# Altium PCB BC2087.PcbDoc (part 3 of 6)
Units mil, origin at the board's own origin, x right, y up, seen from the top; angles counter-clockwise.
Board outline 7401.57 x 1181.1 mil, 6 copper layers (Top Copper, Signal Layer 1, Signal Layer 2, Signal Layer 3, Signal Layer 4, Bottom Copper), stack 62.874 mil thick; 302 components, 237 nets, 1184 pads, 867 vias.
Unrouted connection lines stored in the file: 315.
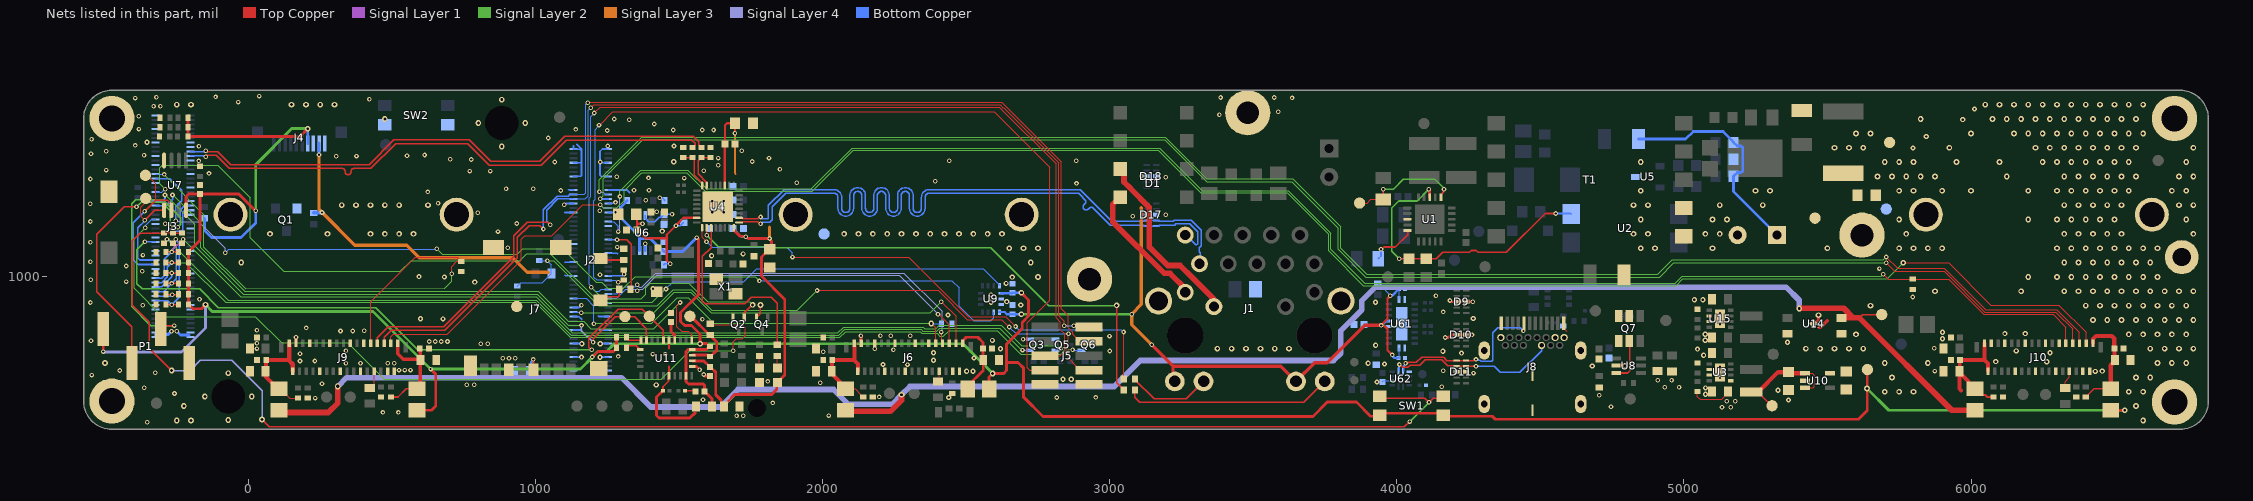
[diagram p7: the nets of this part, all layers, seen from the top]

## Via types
v1: diameter 20, hole 10, Top Copper to Bottom Copper, 273 vias
v2: diameter 16, hole 8, Top Copper to Bottom Copper, tented both sides, 243 vias
v3: diameter 15.98, hole 7.99, Top Copper to Bottom Copper, tented both sides, 201 vias
v4: diameter 18, hole 8, Top Copper to Bottom Copper, tented both sides, 70 vias
v5: diameter 16, hole 7.95, Top Copper to Bottom Copper, tented both sides, 36 vias
v6: diameter 20, hole 10, Top Copper to Bottom Copper, tented both sides, 26 vias
v7: diameter 16, hole 8, Top Copper to Bottom Copper, 17 vias
v8: diameter 19.68, hole 11.81, Top Copper to Bottom Copper, tented both sides, 1 vias

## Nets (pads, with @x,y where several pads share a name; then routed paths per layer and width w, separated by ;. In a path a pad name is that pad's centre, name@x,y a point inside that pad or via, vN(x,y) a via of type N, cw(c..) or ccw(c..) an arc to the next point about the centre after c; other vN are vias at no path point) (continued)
1V8: C12.2 C18.2 C19.2 C52.2 C60.2 C120.2 FB5.1 FB8.1 FB11.1 J4.7 P1.1 R1.2 R2.2 R7.2 R9.2 R16.2 R31.2 R50.2 R68.2 R72.1 R73.1 R79.1 R128.2 R129.2 R130.2 SW1.2 SW1.4 TP16.1 U6.3 U7.8 U9.5 U10.5 U11.5 U11.28 | length 11933.2
  Top Copper w10: P1.1@-506.43,818.06 -506.43,740.43 v2(-506,740) ; U7.8@-217.52,1232.28 -217.52,1280.29 -208.68,1289.13 C120.2@-169.29,1289.13 ; R130.2@-210.63,1554.35 -211.12,1553.85 -211.12,1489.67 R129.2@-211.61,1489.17 179.17,1489.17 v6(206,1516) ; v6(-150,903.41) -164.41,889 -194.06,889 R1.2@-208.66,903.6 R2.2@-208.66,939.96 R7.2@-208.66,977.36 R9.2@-208.66,1013.78 R16.2@-208.66,1050.2 R68.2@-208.66,1086.61 -208.66,1088.58 -169.29,1127.95 C120.2@-169.29,1289.13 ; v5(25,1230) -34.13,1289.13 C120.2@-169.29,1289.13 ; FB8.1@586.61,535.43 637.43,535.43 652,550 652,661 v5(634,679) ; v5@1197.86,721 1216.86,740 1270.25,740 1281.28,751.03 R73.1@1281.28,753 R72.1@1281.28,790 ; v5(1561,1137) 1567,1131 1567,938 1505,876 1505,845 1519.21,830.79 1543.2,830.79 1573,800.98 v6(1573,767) 1574.05,768.05 1594.7,768.05 R31.2@1605.03,757.72 ; R31.2@1607,757.72 R31.2@1605.03,757.72 ; C18.2@1614.32,548.35 1614.32,575.43 C19.2@1588.75,601 1588.75,622.39 1584.14,627 1532,627 1523.9,635.1 U11.28@1523.9,656 1523.9,740.75 1530.19,747.05 U11.5@1546.04,747.05 1594.36,747.05 R31.2@1605.03,757.72 ; FB11.1@2579.61,610.24 2579.61,651.55 v6(2592,663.94) 2630.47,663.94 2640,673.47 2640,701.74 ; v6(2691.86,944.88) 2717,919.75 2717,863.6 2695,841.6 2695,820.59 2640,765.59 2640,701.74 ; 5638.56,536.95 5638.56,534.56 ; TP16.1@5638.56,676.56 5638.56,534.56 ; FB5.1@6486.76,535.43 v6(6535.57,535.43) ; 2640,701.74 2680.26,701.74 2700,682 2700,581 2767,514 3707.62,514 3757.62,564 3859,564 3908.24,514.76 3937.08,514.76 3941,510.84 3955.16,525 4147.32,525 4161.47,510.84 4165.39,514.76 4332.24,514.76 4343,504 5608,504 5638.56,534.56
  Signal Layer 2 w10: v6(-150,903.41) -126.59,880 433,880 v5(634,679) 1156,679 v5@1197,720 ; v5(25,1230) 25,1391 150.5,1516.5 205.5,1516.5 v6(206,1516) ; v5(1197,721) 1216,740 1247,740 1274,767 v6(1573,767) 2488.94,767 v6(2592,663.94) ; v6(5638,611) 5713.57,535.43 v6(6535.57,535.43)
  Signal Layer 4 w10: v2(-506,740) -504,738 -233.56,738 -150,821.56 v6(-150,903.41)
  Bottom Copper w10: R79.1@-153.29,1203.61 -153.29,1161.6 -128.7,1137 -26,1137 25,1188 v5(25,1230) ; J4.7@206.03,1465.03 v6(206,1516) ; R50.2@1318.5,1266.18 1318.5,1264.21 1297.68,1243.39 1297.68,1205.5 1362.09,1141.09 1362.09,1133 ; U6.3@1362.09,1092.12 1362.09,1133 ; v5(1561,1137) 1512.18,1088.18 C52.2@1446.73,1088.18 1439.53,1095.39 1437.61,1095.39 1400,1133 1362.09,1133 ; U9.5@2621.71,942.91 2621.79,942.99 2659.53,942.99 C12.2@2661.42,944.88 v6(2691.86,944.88)
  other v4: 2527,717.75
1V8_CAM_M: C71.2 C72.2 FB11.2 J6.1 | length 275.2
  Top Copper w9.84: J6.1@2488.04,768.34 2489.02,769.32 2489.02,778.54 2500.07,789.59 2540.21,789.59 2557.84,771.95 C71.2@2557.84,750.22 2558.54,749.52 C72.2@2558.54,711.24 ; FB11.2@2504.81,610.24 2504.81,619.67 2559.23,674.1 C72.2@2559.23,710.55
1V8_L: C80.2 C81.2 FB5.2 J10.1 R35.1 | length 379
  Top Copper w5.91: R35.1@6399.75,581.69 6401.72,581.69 6407.63,587.6 6407.63,589.57 6428.29,610.24 FB5.2@6486.76,610.24
  Top Copper w15: J10.1@6425.05,768.34 6425.2,768.49 6425.2,783.46 6435.77,794.04 6490.43,794.04 6499.22,785.25 C80.2@6499.22,750.22 6500.2,749.23 6500.2,711.53 C81.2@6501.19,710.55 6501.19,706.61 6486.76,692.18 FB5.2@6486.76,610.24
1V8_R: C86.2 C87.2 FB8.2 J9.1 R40.1 | length 372.5
  Top Copper w5.91: R40.1@495.79,581.69 520.67,581.69 549.21,610.24 FB8.2@586.61,610.24
  Top Copper w11.81: J9.1@519.54,768.34 519.54,732.28 539.22,712.6 596.49,712.6 C87.2@598.55,710.55 ; FB8.2@586.61,610.24 598.43,622.05 598.43,710.42 C87.2@598.55,710.55 ; C86.2@596.46,750.22 597.5,749.17 597.5,711.59 C87.2@598.55,710.55
2V8: C66.2 FB4.1 FB7.1 FB10.1 TP23.1 U14.1 | length 6907.7
  Top Copper w5.91: 5611.22,857.28 5622.54,868.6 TP23.1@5688.98,868.6
  Top Copper w11.81: 5470.47,823.82 5475.39,823.82 5499.02,847.44
  Top Copper w19.68: FB7.1@106.3,535.43 114.17,527.56 277.63,527.56 310.93,560.86 v8(310.93,618.46) ; FB10.1@2079.46,535.43 2083.39,531.5 2236.22,531.5 2274.55,569.82 2274.55,589.51 v6(2274.61,589.57) ; v6@5401.68,889.87 5401.72,889.82 5402.64,890.75 5556.86,890.75 5590.32,857.28 ; C66.2@5549.21,857.28 5590.32,857.28 ; FB4.1@6013.85,535.43 5933.07,535.43 5611.22,857.28 5590.32,857.28
  Signal Layer 4 w19.68: v8(310.93,618.46) 341.47,649 1298.88,649 1400.88,547 1643.38,547 1704.38,608 2038,608 2090,556 2241.04,556 v6(2274.61,589.57) ; v6@2274.55,589.63 v6(2274.61,589.57) ; v6(5401.57,889.76) 5401.57,918.53 5355.54,964.57 3925.2,964.57 3877.95,917.32 3877.95,885.83 3805.12,812.99 3805.12,734.25 3779.53,708.66 3106.3,708.66 3015.75,618.11 2653.54,618.11 2653.19,618.46 2303.5,618.46 v6(2274.61,589.57)
2V8_CAM_M: C75.2 C77.2 FB10.2 J6.32 J6.33 R60.1 | length 373.9
  Top Copper w4: FB10.2@2079.46,610.24 2112.68,610.24 2132.63,590.29 2132.63,588.32 2139.49,581.46 R60.1@2141.46,581.46
  Top Copper w13.78: FB10.2@2079.46,610.24 2079.46,614.23 2031.6,662.09 C77.2@2031.6,671.48 2032.38,672.26 2032.38,709.76 C75.2@2033.16,710.55 2108.33,710.55 ; J6.33@2110.09,768.34 2110.09,712.3 2108.33,710.55 ; J6.32@2122.19,671.88 2122.19,696.68 2108.33,710.55
2V8_L: C82.2 C83.2 FB4.2 J10.32 J10.33 R71.2 | length 454.7
  Top Copper w7.87: FB4.2@6013.85,610.24 6035.5,588.58 6049.3,588.58 6056.19,581.69 R71.2@6078.82,581.69
  Top Copper w13.78: 5965.8,604.89 5959.74,610.95 C83.2@5959.74,667.54 ; FB4.2@6013.85,610.24 6009.91,610.24 5991.21,628.94 5991.21,636.07 C83.2@5959.74,667.54 ; J10.33@6047.1,768.34 6047.1,710.55 ; J10.32@6059.2,671.88 6059.2,698.44 6047.1,710.55 ; C83.2@5959.74,667.54 C83.2@5959.74,671.48 5960.72,672.46 5960.72,709.56 C82.2@5961.71,710.55 6047.1,710.55
2V8_R: C88.2 C89.2 FB7.2 J9.32 J9.33 R41.2 | length 383.7
  Top Copper w4: FB7.2@106.3,610.24 110.24,610.24 142.72,577.76 R41.2@172.6,577.76
  Top Copper w15: FB7.2@106.3,610.24 102.36,610.24 59.47,653.13 C89.2@59.47,671.48 60.45,672.46 60.45,709.56 C88.2@61.44,710.55 138.67,710.55 ; J9.33@141.58,768.34 141.58,713.46 138.67,710.55 ; J9.32@153.69,671.88 153.69,695.52 138.67,710.55
3V3: C10.2 C15.2 C16.2 C17.2 C21.2 C34.2 C38.2 C39.2 C40.2 C41.2 C53.2 C55.2 C58.2 C59.2 C74.2 C97.2 D16.2 J1.15 J1.17 J4.9 J7.4 L4.2 R28.1 R29.1 R33.2 R46.1 R49.1 R186.2 TP7.1 U3.5 U4.11 U4.23 U4.32 U6.7 U9.8 U10.1 U10.3 U11.3 U61.1 U61.6 U61.10 | length 6595.4
  Top Copper w4: R33.2@5047.24,600.7 5047.24,582.76 5057,573 5132.39,573 5153.54,594.15 C15.2@5153.54,600.7 ; U10.3@5422.24,613.35 5450.79,613.35 5454.72,617.28 5454.72,656.65 5446.85,664.53 U10.1@5422.24,664.53
  Top Copper w5.91: L4.2@5257.87,598.73 TP7.1@5294.44,562.16 ; TP7.1@5295.28,562.99 TP7.1@5300.68,557.58 ; TP7.1@5300.68,560.29 TP7.1@5300.68,557.58 ; TP7.1@5307.09,551.18 TP7.1@5300.68,557.58
  Top Copper w7.87: v3(992.13,712.6) 992.13,676.4 J7.4@992.34,676.18 ; C21.2@1352.66,1219.93 1352.66,1186.71 ; v3(1372.32,1185.63) 1353.74,1185.63 1352.66,1186.71 ; v3(1468.5,1046) 1468.5,1046.46 1456.81,1058.15 1456.81,1134.91 ; U4.23@1561.32,1205.67 1515.21,1205.67 1488.83,1179.29 v3(1488.83,1178.46) 1487.94,1178.46 1456.81,1147.33 1456.81,1134.91 ; C40.2@1657.52,1464.3 C40.2@1659.58,1462.25 ; U4.11@1658.76,1318.86 1658.76,1461.43 C40.2@1659.58,1462.25 ; v3(1694.2,1500.23) 1694.04,1500.39 C39.2@1694.04,1535 1666.32,1535 1659.58,1528.26 C40.2@1659.58,1462.25 ; v3(3945.31,831) 3945.31,832.28 v3@3949.41,836.38 ; v3(3976.51,933.95) 3967.36,924.81 3967.36,854.33 v3@3949.41,836.38 ; v3(3983.61,728.35) 3967.36,744.59 3967.36,818.43 v3@3949.41,836.38 ; 1352.66,1186.71 C34.2@1352.66,1163.86 1381.61,1134.91 1456.81,1134.91
  Top Copper w9.84: U4.32@1691.24,1162.36 1712.19,1141.41 1731.11,1141.41 v3(1732.28,1140.24) 1733.95,1140.24 1740.32,1133.86 v3(1814.96,1133.86) 1814.96,1132.19 1821.49,1125.67 1821.49,1102.76 C38.2@1814.96,1096.24 1812.99,1096.24 1786.35,1069.6 1786.35,1003.1 1867.72,921.74 1867.72,658.62 D16.2@1841.97,632.87
  Top Copper w10: U11.3@1546.04,707.68 1585.07,707.68 C17.2@1607,685.75 1612.24,680.51 1614.49,680.51 1627.24,667.76 1627.24,589.76 1646.66,570.34 1646.66,557.13 C16.2@1655.44,548.35 1655.44,552.29 1664.22,561.07 1664.64,561.07 1694.57,591 1823,591 1839.98,607.98 1839.98,630.89 D16.2@1841.97,632.87
  Top Copper w11.81: v3(3145.67,763.78) 3220.26,689.19 ; J1.15@3226.57,635.89 3220.26,642.2 3220.26,689.19 ; v3(3945.31,831) 3887.35,831 3757.14,700.79 3713.52,700.79 J1.17@3648.62,635.89 3595.32,689.19 3220.26,689.19
  Top Copper w15.75: L4.2@5234.25,598.73 5257.87,598.73 5327.83,668.69 C59.2@5364.17,668.69 5368.33,664.53 U10.1@5422.24,664.53
  Signal Layer 2 w10: v6(2691.86,870.08) 3075.64,870.08 v3(3076,870.44)
  Signal Layer 3 w5: 1812.94,1176.07 1814.96,1174.05
  Signal Layer 3 w5.91: v3(1694.2,1500.23) 1694.2,1360.81 1696.33,1358.67
  Signal Layer 3 w9.84: v3(1814.96,1133.86) 1814.96,1174.05
  Signal Layer 3 w11.81: v3@245.43,1424.06 245.43,1234.88 v3(255.77,1224.54) 370.08,1110.24 551.18,1110.24 594.49,1066.93 920.18,1066.93 971.36,1015.75 1043.31,1015.75 ; 3110,1240.73 3110,904.44 v3(3076,870.44) 3076,833.45 v3(3145.67,763.78)
  Bottom Copper w4: R186.2@3933.54,977.26 3942.37,968.44 3945.31,968.44 v3@3974.21,939.53 ; v3@3974.21,939.49 v3@3976.47,937.24 ; C97.2@4006.09,956.69 C97.2@4006.88,956.69 4007.52,956.05 U61.10@4007.52,921.55 ; C58.2@4006.34,717.61 4007.52,718.79 U61.1@4007.52,752.26
  Bottom Copper w4.02: v3(3976.51,933.95) v3@3976.51,937.24
  Bottom Copper w5: U6.7@1381.77,1214.17 1381.77,1204.32 1389.05,1197.04 1389.05,1195.73 1392.86,1191.92 1414.76,1191.92 1431.33,1208.49 1437.12,1208.49 C53.2@1446.73,1218.1 1447.26,1218.63 v3(1475.13,1218.63) ; v3(1488.83,1178.46) 1503.26,1178.46 1513.78,1188.98 R29.1@1515.75,1188.98 ; C41.2@1688.2,1169.33 1716.79,1140.74 1731.78,1140.74 v3(1732.28,1140.24)
  Bottom Copper w5.91: v3(1432.28,1275.59) 1440.94,1275.59 1448.82,1267.72 R49.1@1448.82,1266.18 ; R46.1@1446.73,1042.91 1449.82,1046 v3(1468.5,1046) ; C74.2@3885.83,834.65 3889.47,831 v3(3945.31,831) 3947.24,832.93 3951.38,832.93 3965.2,846.75 U61.6@3972.09,846.75
  Bottom Copper w7.87: C55.2@984.25,669.69 984.25,702.53 992.13,710.4 v3(992.13,712.6) ; U9.8@2615.31,877.46 2633.8,877.46 2641.18,870.08 C10.2@2661.42,870.08 v6(2691.86,870.08) ; v3(3976.51,933.95) 3978.06,935.51 3984.9,935.51 C97.2@4006.09,956.69 ; v3(3983.61,728.35) 3985.16,726.79 3985.16,724.42 3991.98,717.61 C58.2@4006.34,717.61
  Bottom Copper w11.81: R28.1@226.42,1222.99 253.09,1222.99 254.64,1224.54 v3(255.77,1224.54) ; v3(245.43,1425.2) J4.9@245.43,1465
  other v2: 5132.68,545.77 5163.39,545.77 5149.61,566.93 5178.35,566.93
5V_LED: D6.2 R55.1 | length 44
  Top Copper w4: R55.1@1779.53,724.41 1779.53,686.02 D6.2@1783.46,682.09
5V_PoE: C7.1 C9.2 C26.2 L1.2 Q7.1 Q7.2 Q7.5 Q7.6 R14.2 R24.2 TP6.1 U8.3 | length 942.6
  Top Copper w5.91: U8.3@4763.78,665.35 4804.68,665.35 4811.39,672.07 4811.39,776.21 Q7.2@4810.04,777.56
  Bottom Copper w9.84: C26.2@4842.09,1480.31 5006.01,1480.31 5032.71,1507.02 5136.68,1507.02 5173.23,1470.47 R14.2@5173.23,1468.5 5173.23,1468.43 5186.02,1455.64 5198.96,1455.64 5204.72,1449.87 5204.72,1369.02 5198.96,1363.26 5186.02,1363.26 5173.23,1350.46 R24.2@5173.23,1350.39 5173.23,1297.24 C7.1@5324.8,1145.67
2485_PGOOD: J2.37 J5.5 Q2.1 | length 3825.1
  Top Copper w4.02: v3(1204.4,1571.11) 1224.62,1591.33 2615.26,1591.33 2812.99,1393.6 2812.99,857.71 2827.86,842.84 2827.86,816.81 2842.29,802.38 2842.29,773.56 2842.43,773.41 2842.43,741.18 2826.65,725.39 J5.5@2774.61,725.39
  Top Copper w5: Q2.1@1726.68,859.02 1726.68,875.6 1753.84,902.75 v6(1756,902.75)
  Signal Layer 2 w4.02: v3(1194,964) 1234,924 1367.98,924 1384,940.02 1384,963 1399,978 1534,978 1599,913 1745.75,913 v6(1756,902.75)
  Bottom Copper w4.02: v3(1204.4,1571.11) 1204.4,1570.55 1191.36,1557.51 1191.36,1279.64 1186.72,1275 1186.72,974.51 1194,967.24 v3(1194,964) 1207.44,950.56 1221.91,950.56 1228.04,956.69 J2.37@1252.95,956.69
2485_WAKEUP: J2.41 J5.7 R62.1 | length 3119.3
  Top Copper w4.02: v3(1220.54,1528.98) 1223.07,1528.98 1269.38,1575.3 2597.93,1575.3 2791.34,1381.89 2791.34,918.31 2712.6,839.57 2712.6,684.13 2721.34,675.39 J5.7@2774.61,675.39
  Top Copper w6: v3(1287.4,981.49) 1289.31,983.4 1301.76,983.4 R62.1@1307.09,988.73
  Bottom Copper w4.02: v3(1220.54,1528.98) 1220.54,1525.86 1208.09,1513.41 1208.09,1271.25 1202.76,1265.92 1202.76,999.02 1212.05,989.72 1251.42,989.72 1254.49,986.65 1256.02,988.19 1277.46,988.19 1284.16,981.49 v3(1287.4,981.49)
BMI270_INT_1V8: J3.66 U9.4 | length 3456.8
  Signal Layer 2 w4: v5(-290.42,1305.59) -310,1325.17 -310,1380 -301.35,1388.65 -107.15,1388.65 6.18,1275.32 6.18,1136 123.18,1019 529,1019 566.61,1056.61 944.61,1056.61 969.43,1081.43 1051.57,1081.43 1222,911 1407,911 v2(1454,958)
  Bottom Copper w4: -309.72,1295.28 -302.35,1295.28 -292.03,1305.59 v5(-290.42,1305.59) ; v2(1454,958) 1479.42,983.42 1724.42,983.42 1770,1029 2559.74,1029 2615.31,973.43 U9.4@2615.31,969
  Bottom Copper w5: J3.66@-324.02,1295.28 -309.72,1295.28
BMI270_WAKE_1V8: J3.72 U9.9 | length 3348.3
  Signal Layer 2 w4: v3(655.51,1098.43) 674.94,1079 936.73,1079 955.17,1097.44 1094.51,1097.44 1210.95,981 1231,981 1252,960 1305.44,960 1346.86,1001.42 1764.11,1001.42 v3(1779.53,986)
  Signal Layer 4 w4: v3(-253.94,1195.8) -251.64,1193.5 -242.23,1193.5 -241.28,1192.55 -174.35,1192.55 -81.69,1099.9 v3(-81.69,1084.65)
  Bottom Copper w4: v3(-81.69,1084.65) -80.4,1084.65 -68.59,1096.46 653.54,1096.46 v3(655.51,1098.43) ; v3(1779.53,986) 1780.53,987 2449.91,987 2475,961.91 2475,898.5 2526.5,847 2585,847 2595.63,857.63 U9.9@2595.63,877.46
  Bottom Copper w5: J3.72@-324.02,1342.52 -300.01,1342.52 -274.42,1342.51 -233,1301.09 -233,1264.99 -253.94,1244.05 v3(-253.94,1195.8)
BNO08x_BOOTN_1V8: J3.54 R32.2 | length 2775.7
  Top Copper w4: R32.2@1608,836.69 1611.68,833 1721.42,833 1730.42,824 1730.42,795.42 1719,784 1698.4,784 1688,773.6 v2(1688,742.95)
  Signal Layer 2 w4: v2(-360,1171.49) -398,1133.49 -398,960 -300,862 24,862 116,770 346.28,770 472.36,643.92 1436.92,643.92 1535.95,742.95 v2(1688,742.95)
  Bottom Copper w4: v2(-360,1171.49) -360,1178.39 -337.6,1200.79 J3.54@-324.02,1200.79
BNO08x_BOOTN_1V8_1: R31.1 R32.1 TP26.1 U11.4 | length 258.9
  Top Copper w10: TP26.1@1537,862.91 1540.44,862.91 1606.03,797.32 R32.1@1609.97,797.32 ; U11.4@1546.04,727.36 1599.95,727.36 1605.03,722.28 1608.97,722.28 1631,744.32 1631,773 1608,796 R32.1@1608,797.32
BNO08x_INT_1V8: J3.62 TP35.1 U11.14 | length 2095.1
  Top Copper w5: v5(1200,772) v5(1200,772) 1199.96,783.96 1277.91,861.91 TP35.1@1311.02,861.91 1344.37,861.91 1386.1,820.17 U11.14@1386.1,779.04
  Signal Layer 2 w4: v5(-291,1285.43) -188.3,1182.73 -188.3,1109.3 -18,939 1004.89,939 1112.89,831 v5(1159.74,831)
  Signal Layer 4 w5: v5(1159.74,831) 1159.51,830.76 1159.51,812.49 v5(1200,772)
  Bottom Copper w5: J3.62@-324.02,1263.78 -301.64,1263.78 -291,1274.42 v5(-291,1285.43)
BNO08x_RSTn_1V8: J3.44 TP34.1 U11.11 | length 2285.2
  Top Copper w5: v5(1195,746) 1193.78,746 1185.5,754.28 1185.5,785.5 1288.09,888.09 1370.81,888.09 1445.16,813.75 U11.11@1445.16,779.04
  Signal Layer 2 w5: v5(-361.07,1122.05) -389,1094.12 -389,977 -370,958 -170,958 -105,893 443,893 590,746 v5(1195,746)
  Bottom Copper w6: v5(-361.07,1122.05) J3.44@-324.02,1122.05
BNO08x_WAKE_1V8: J3.60 U11.6 | length 2302.7
  Top Copper w4: v2(1503,911) 1492,900 1492,827.22 1509.12,810.1 1531.73,810.1 1543.58,798.24 U11.6@1543.58,779.04
  Signal Layer 2 w4: v5(-265,1285.28) -263.28,1285.28 -166,1188 -166,1102 -13.5,949.5 1008.32,949.5 1112.82,845 1167,845 1192,820 1412,820 v2(1503,911)
  Bottom Copper w5: J3.60@-324.02,1248.03 -287.97,1248.03 -265,1271 v5(-265,1285.28)
BOOT0/LED_B: J3.26 Q6.1 R16.1 R23.2 | length 3489
  Top Copper w5: R23.2@-287.4,1050.2 v3(-267.81,1050.2) R16.1@-246.06,1050.2
  Signal Layer 2 w4: v3(-267.81,1050.2) -219.2,1050.2 -80,911 998.95,911 1107.95,802 1120.95,789 2059.63,789 2079.63,809 2339.69,809 2345.69,803 2398.45,803 2408.1,793.35 2420.73,793.35 2440.38,813 2607.38,813 2689.3,731.08 2828.91,731.08 2843.7,745.87 v3(2870.25,745.87)
  Bottom Copper w4: v3(2870.25,745.87) 2871.14,744.98 2901.28,744.98 Q6.1@2902.17,744.09
  Bottom Copper w5: J3.26@-324.02,980.32 -302.39,980.32 -282.92,999.79 -282.92,1034.08 -267.81,1049.19 v3(-267.81,1050.2)
BOOT1: J3.24 R9.1 R22.2 | length 126
  Top Copper w5: R22.2@-287.09,1013.78 v3(-267.81,1013.78) ; v3@-267.81,1012.73 -247.11,1012.73 R9.1@-246.06,1013.78
  Bottom Copper w5: J3.24@-324.02,964.57 -322.97,965.61 -302.39,965.61 -267.81,1000.19 v3(-267.81,1013.78)
BOOT2/LED_R: J3.22 Q3.1 R7.1 R21.2 R45.2 | length 3497.7
  Top Copper w5: R45.2@-294.29,1117.13 -292.32,1117.13 -285.96,1123.49 -285.96,1129.91 v3(-284.17,1131.7) ; R21.2@-287.09,977.36 v3(-267.81,977.36) R7.1@-246.06,977.36
  Signal Layer 2 w4: v3(-284.17,1131.7) -71.47,919 1002.26,919 1110.26,811 1124.26,797 2056.31,797 2076.31,817 2343,817 2349,811 2396.75,811 2407.59,821.84 2617.16,821.84 2693.92,745.08 v3(2695.87,745.08)
  Bottom Copper w4: v3(2695.87,745.08) 2696.36,744.59 2722.15,744.59 Q3.1@2722.64,744.09
  Bottom Copper w5: J3.22@-324.02,948.82 -296.35,948.82 v3(-267.81,977.36) -252,993.17 -252,1102.21 -281.5,1131.7 v3(-284.17,1131.7)
BOOT3: J3.20 R2.1 R20.2 | length 104.9
  Top Copper w5: R20.2@-287.09,939.96 -285.12,937.99 v3(-265.75,937.99) -246.06,937.99 R2.1@-244.09,939.96
  Bottom Copper w5: J3.20@-324.02,933.07 -273.65,933.07 -268.72,937.99 v3(-265.75,937.99)
BOOT4: J3.18 R1.1 R19.2 R44.2 | length 368.8
  Top Copper w5: R19.2@-287.4,903.6 -287.21,903.41 v3(-267.67,903.41) ; v3@-267.67,903.6 -246.06,903.6 R1.1@-246.06,905.57 ; R44.2@-262.8,1117.13 -260.83,1117.13 -254.47,1123.49 -254.47,1130.89 v3(-253.66,1131.7)
  Bottom Copper w5: J3.18@-324.02,917.32 -281.58,917.32 v3(-267.67,903.41) -242,929.08 -242,1117.06 -253.66,1128.72 v3(-253.66,1131.7)
BOOT7/LED_G: J3.28 Q5.1 R68.1 R80.2 R81.2 | length 3507.7
  Top Copper w5: R81.2@-287.4,1087.01 v3(-267.67,1087.01) -244.49,1087.01 R68.1@-244.09,1086.61 ; R80.2@-232.28,1117.13 -228.26,1121.15 v3(-228.26,1131.7)
  Signal Layer 1 w5: v3(-267.67,1087.01) -265.56,1089.11 -265.56,1094.4 v3(-228.26,1131.7)
  Signal Layer 2 w4: v3(-228.26,1131.7) -27.56,931 1001.57,931 1127.57,805 2053,805 2073,825 2351,825 2356,820 2394.43,820 2405.43,831 2622.76,831 2693.18,760.59 2818.23,760.59 v3(2828.42,750.39)
  Bottom Copper w4: Q5.1@2811.61,744.09 2815.52,748 2822.98,748 2825.37,750.39 v3(2828.42,750.39)
  Bottom Copper w5: J3.28@-324.02,996.06 -301.92,996.06 -294,1003.98 -294,1060.67 v3(-267.67,1087.01)
BOOTSEL: R44.1 R45.1 R80.1 SW1.1 SW1.3 | length 5510.2
  Top Copper w5: v6(-268,674) -345.36,751.36 -345.36,841.36 -405,901 -405,1125.38 -377.82,1152.56 R45.1@-294.29,1152.56 -293.31,1153.54 -263.78,1153.54 R44.1@-262.8,1152.56 R80.1@-232.28,1152.56 ; v6(47,503) 72.57,477.43 4026.42,477.43 v7(4044.99,496) ; SW1.3@3941,577.77 4097.98,577.77 v7(4111.96,563.79) 4125.94,577.77 SW1.1@4161.47,577.77
  Signal Layer 2 w5: v7(4044.99,496) 4112,563.01 v7(4111.96,563.79) v7(4111.96,563.79)
  Signal Layer 4 w5: v6(-268,674) -204,674 -169,709 -59,709 47,603 v6(47,503)
BRIDGE_REFCLK_N: J3.81 R25.2 | length 1932.1
  Top Copper w5.12: v3(-149.61,1419.02) -145.43,1423.19 -112.8,1423.19 -67.76,1378.14 302.17,1378.14 325.59,1378.14 cw(c325.59,1367.71) 336.02,1367.71 336.02,1366.36 ccw(c346.46,1366.36) 346.46,1355.93 ccw(c346.46,1366.36) 356.89,1366.36 356.89,1367.71 cw(c367.32,1367.71) 367.32,1378.14 397.64,1378.14 425.39,1378.14 511.81,1464.57 763.04,1464.57 837.84,1389.76 1019.69,1389.76 1106.3,1476.38 1544.2,1476.38 1555.18,1465.4 1555.18,1460.64 R25.2@1545.91,1451.37
  Bottom Copper w5.12: J3.81@-202.76,1421.26 -201.28,1422.74 -153.33,1422.74 v3(-149.61,1419.02)
BRIDGE_REFCLK_P: J3.83 R6.2 | length 1926.2
  Top Copper w5.12: v3(-149.61,1439) -146.58,1435.98 -107.5,1435.98 -62.46,1390.93 420.09,1390.93 506.51,1477.36 768.33,1477.36 843.14,1402.55 1014.39,1402.55 1101,1489.17 1549.5,1489.17 1567.97,1470.7 1567.97,1460.64 R6.2@1577.24,1451.37
  Bottom Copper w5.12: J3.83@-202.76,1437.01 -201.28,1435.53 -153.08,1435.53 v3(-149.61,1439)
CAM_A_CLK_OUT: J2.28 J6.3 | length 1523.8
  Top Copper w4.02: v3(2413.39,913.39) 2464.42,862.35 J6.3@2464.42,768.34
  Signal Layer 2 w4.02: v3(1159.3,875) 1412,875 1483,946 1540,946 1611,875 2375,875 v3(2413.39,913.39)
  Bottom Copper w4.02: J2.28@1131.69,877.95 1133.17,876.48 1157.82,876.48 v3(1159.3,875)
CAM_A_PWDN_N: J2.34 J6.9 R70.2 | length 1506.2
  Top Copper w4: v6(2378,838) 2393.55,822.45 J6.9@2393.55,768.34
  Signal Layer 2 w4: v5(1203,837) 1204,838 1404,838 1493,927 1531,927 1620,838 v6(2378,838)
  Bottom Copper w4: J2.34@1131.69,925.2 1176.46,925.2 1203,898.65 v5(1203,837) ; v6(2378,838) 2379.24,836.76 R70.2@2414.48,836.76
CAM_B_CLK_OUT: J2.73 J9.3 J10.3 | length 6757.2
  Top Copper w4: J9.3@495.91,768.34 495.91,791.36 504.55,800 692,800 949.91,1057.91 949.91,1130.73 962.56,1143.37 1056.69,1143.37 1164.78,1251.46 v5(1224.85,1251.46) ; v6(5764,1049.43) 5921.66,1049.43 6069.1,902 6306,902 6401.43,806.57 J10.3@6401.43,768.34
  Signal Layer 2 w4: v5(1224.85,1251.46) 1236.15,1240.16 1283.16,1240.16 1308,1265 1308,1300.62 1370.29,1362.91 1527,1362.91 1591.61,1298.31 1963.31,1298.31 2105.82,1440.82 3169.18,1440.82 3317,1293 3617.69,1293 3762,1148.69 3762,1091.2 3883.2,970 4973.44,970 4996.44,993 5707.57,993 v6(5764,1049.43)
  Bottom Copper w4: v5(1224.85,1251.46) 1236.15,1240.16 J2.73@1252.95,1240.16
CAM_B_D_PWM: J2.65
CAM_B_PWDN_N: J2.67 J10.9 R37.1 | length 5728.7
  Top Copper w4: v2(5694.53,1009) 5711.4,992.13 5921.62,992.13 6044.05,869.7 6285.98,869.7 6330.56,825.12 J10.9@6330.56,768.34
  Signal Layer 2 w4: v3(1293.66,1280) 1293.66,1297.59 1366.98,1370.91 1530.66,1370.91 1595.27,1306.31 1960,1306.31 2102.51,1448.82 2103.82,1448.82 3174.18,1448.82 3322,1301 3621,1301 3770,1152 3770,1097 3889,978 4970.13,978 4994.13,1002 5687.53,1002 v2(5694.53,1009)
  Signal Layer 4 w4: v3(1287.4,1157.87) 1287.4,1159.95 1293.66,1166.21 v3(1293.66,1280)
  Bottom Copper w4: J2.67@1252.95,1192.91 1271.65,1192.91 1287.4,1177.17 v3(1287.4,1157.87)
CAM_R_PWM: J3.74 J9.9 R43.2 | length 1898.2
  Top Copper w4: J9.9@425.05,768.34 425.05,913.05 580,1068 726.75,1068 R43.2@740.89,1053.86 725.44,1053.86 707,1035.42 707,1012 v5(708,1011)
  Signal Layer 2 w4: v3(-294,1357) -294,1356 -155.31,1217.31 -155.31,1103.31 -10,958 683.4,960.56 708,985.15 v5(708,1011)
  Bottom Copper w4: J3.74@-324.02,1358.27 -323.38,1357.63 -294.63,1357.63 v3(-294,1357)
CAP: C20.1 U11.9 | length 69.8
  Top Copper w10: C20.1@1471,843.25 1471,810.1 1484.53,796.57 U11.9@1484.53,779.04
CC1: D11.5 D11.6 J8.A5 U62.2 | length 594.8
  Top Copper w5: v5(4030.26,699.31) 4032.37,701.42 4040.14,701.42 4040.64,701.91 4068.06,701.91 4086.46,720.31 4162.65,720.31 4174.3,708.66 D11.6@4207.97,708.66 D11.5@4240.85,708.66 4268.68,708.66 4272.61,712.6 v3(4275.59,712.6) ; v3(4440.94,811.84) 4441.93,812.82 4441.93,837.1 J8.A5@4442.91,838.08
  Bottom Copper w5: U62.2@4023.62,671.55 4023.62,691.3 4030.26,697.94 v5(4030.26,699.31) ; v3(4275.59,712.6) 4277.7,710.49 4288.59,710.49 4293.48,705.6 4329.96,705.6 4334.65,710.29 4334.65,805.07 4352.26,822.69 4429.88,822.69 4440.73,811.84 v3(4440.94,811.84)
CC2: D11.4 D11.7 J8.B5 U62.1 | length 609.4
  Top Copper w5: v5(4008.81,694.88) 4010.6,694.88 4020.66,684.81 4038.52,684.81 4046.62,692.91 4079.79,692.91 4098.19,711.31 4156.47,711.31 4177.82,689.96 4206.99,689.96 D11.7@4207.97,688.98 D11.4@4240.85,688.98 v3(4275.59,688.98)
  Signal Layer 2 w5: v3@4275.59,686.74 v3(4275.59,688.98) ; J8.B5@4500,757.37 J8.B5@4503.94,761.31
  Bottom Copper w5: U62.1@4007.87,671.55 4008.34,672.02 4008.34,694.41 v5(4008.81,694.88) ; v3(4275.59,688.98) 4338.58,688.98 4359.96,667.59 4428.42,667.59 4503.94,743.11 J8.B5@4503.94,761.31
CD_SW1: J7.9 R66.1 | length 94
  Top Copper w6: J7.9@1226.01,918.31 1239.08,931.38 1287.82,931.38 1291.34,934.9 R66.1@1291.34,956.69
CD_SW2: J7.10 R67.2 | length 88
  Top Copper w5.91: J7.10@1226.01,1059.06 J7.10@1226.01,1063.98 1230.93,1059.06 R67.2@1307.09,1059.06
CLK_N: R25.1 R30.2 U4.16 | length 142.9
  Top Copper w5.12: R30.2@1514.2,1415.9 R25.1@1545.91,1415.93 ; R25.1@1545.91,1415.93 1553.02,1408.82 1553.02,1353.44 1580.02,1326.44 U4.16@1580.02,1318.86
CLK_P: R6.1 R26.2 U4.15 | length 145.7
  Top Copper w5.12: U4.15@1595.77,1318.86 1595.77,1328.78 1565.81,1358.74 1565.81,1404.51 R6.1@1577.24,1415.93 R26.2@1608.73,1415.93
COM_AUX_IO2: J5.8 R39.2 R82.1 R83.1 | length 2417
  Top Copper w4.02: v3(1980.31,952.76) 2402.04,952.76 2503.79,851 2624.39,851 v3(2650,825.39) ; v3(2856.3,801.94) 2854.53,800.17 2854.53,718.05 2882.91,689.67 2882.91,688.35 2895.87,675.39 J5.8@2928.15,675.39
  Signal Layer 2 w4.02: v3(1041,1056) 1063.3,1056 1219.3,900 1424,900 1480,956 1542.05,956 1614.05,884 1911.56,884 v3(1980.31,952.76)
  Bottom Copper w4: R83.1@936,968 947.48,979.48 1022.79,979.48 R39.2@1055.12,1011.81 1055.12,1041.88 v3(1041,1056)
  Bottom Copper w4.02: R82.1@1012.28,1057 1040,1057 v3(1041,1056) ; v3(2650,825.39) 2673.45,801.94 v3(2856.3,801.94)
CT1: D1.2 J1.11 | length 463.6
  Top Copper w19.68: D1.2@3035.79,1277.56 3010,1251.77 3010,1192.41 3190.15,1012.27 3210.05,1012.27 3266.56,955.76 3266.56,946.52 J1.11@3262.6,946.52
CT2: D1.3 J1.12 | length 640.2
  Top Copper w19.68: D1.3@3035.79,1375.98 3049.57,1362.2 3049.57,1330.6 3073.26,1306.91 3073.26,1306.74 3137.7,1242.3 3137.7,1103.92 3201.67,1039.95 3244.9,1039.95 3288.96,995.89 3362.6,922.25 J1.12@3362.6,896.52
ENV_SCL: R72.2 U11.15 | length 55.4
  Top Copper w5: R72.2@1316.72,790 1316.72,788.03 1325.71,779.04 U11.15@1366.42,779.04
ENV_SDA: R73.2 U11.16 | length 57.3
  Top Copper w5: R73.2@1316.72,753 1316.72,754.64 1323.07,761 1350,761 U11.16@1363.96,747.05
EROUT: R12.1 R18.2 U1.3 U2.4 | length 1043.9
  Top Copper w5.91: v3(4007.87,1062.99) R12.1@4042.09,1062.99 R18.2@4102.75,1062.99 4137.1,1062.99 4159.74,1085.63 4252.85,1085.63 4259.03,1091.81 4276.38,1091.81 4282.56,1085.63 4381.14,1085.63 4516.42,1220.91 v3(4553.41,1220.91)
  Top Copper w10: v3(4111.28,1305.05) 4111.28,1303.42 4114.22,1300.48 4114.22,1277.64 U1.3@4114.3,1277.56
  Signal Layer 2 w5.91: v3(4007.87,1062.99) 3981.67,1089.2 3981.67,1239.88 4006.37,1264.58 4070.82,1264.58 v3(4111.28,1305.05)
  Bottom Copper w5.91: v3(4553.41,1220.91) 4605.83,1220.91 U2.4@4607.45,1219.29
FSIN1: J10.8 R75.2 | length 64.7
  Top Copper w4: R75.2@6328.45,613.03 6328.45,635.54 6342.66,649.75 J10.8@6342.66,671.88
FSIN2: J9.8 R77.2 | length 66.4
  Top Copper w4.02: R77.2@422.01,613.69 425.27,613.69 437.15,625.57 J9.8@437.15,671.88
FSIN3: J6.8 R38.2 | length 37.3
  Top Copper w4: R38.2@2402,636.05 2405.66,639.7 J6.8@2405.66,671.88
GND: B1.1 C6.1 C7.2 C9.1 C10.1 C12.1 C13.1 C14.1 C15.1 C16.1 C17.1 C18.1 C19.1 C20.2 C21.1 C25.2 C27.1 C28.1 C34.1 C36.1 C37.1 C38.1 C39.1 C40.1 C41.1 C42.1 C43.1 C44.1 C45.1 C46.1 C47.1 C48.1 C49.1 C50.1 C52.1 C53.1 C55.1 C58.1 C59.1 C60.1 C61.2 C62.2 C65.1 C66.1 C67.1 C68.1 C69.1 C70.1 C71.1 C72.1 C73.1 C74.1 C75.1 C76.1 C77.1 C78.1 C79.1 C80.1 C81.1 C82.1 C83.1 C84.1 C85.1 C86.1 C87.1 C88.1 C89.1 C97.1 C120.1 C207.1 D6.1 D9.3 D9.8 D10.3 D10.8 D11.3 D11.8 D17.3 D17.8 D18.3 D18.8 J1.19 J1.20 J2.1 J2.2 J2.7 J2.8 J2.13 J2.14 J2.19 J2.20 J2.25 J2.26 J2.30 J2.31 J2.43 J2.44 J2.50 J2.53 J2.58 J2.71 J2.72 J2.75 J2.76 J2.81 J2.82 J2.87 J2.88 J2.93 J2.94 J2.99 J2.100 J3.1 J3.2 J3.3 J3.4 J3.13 J3.14 J3.15 J3.16 J3.29 J3.30 J3.32 J3.38 J3.39 J3.40 J3.46 J3.49 J3.52 J3.55 J3.61 J3.67 J3.70 J3.73 J3.78 J3.79 J3.82 J3.85 J3.87 J3.88 J3.94 J3.100 J4.8 J4.10 J5.9 J5.10 J6.2 J6.4 J6.11 J6.12 J6.15 J6.18 J6.21 J6.24 J6.27 J6.31 J7.6 J7.11 J7.12 J7.13 J7.14 J8.A1 J8.A12 J8.B1 J8.B12 J8.G1 J8.Shell J9.2 J9.4 J9.11 J9.12 J9.15 J9.18 J9.21 J9.24 J9.27 J9.31 J10.2 J10.4 J10.11 J10.12 J10.15 J10.18 J10.21 J10.24 J10.27 J10.31 MH1.1 MH2.1 P1.4 pad.2@2929.28,992.13 pad.2@3480.31,1571.85 pad.2@5620.2,1145.67 pad.2@6708.81,564.45 pad.2@6708.81,1551.61 pad.2@6734,1069 pad.2@-476.23,567.36 pad.2@-476.23,1551.61 pad.3 Q1.2 Q2.2 Q3.2 Q4.2 Q5.2 Q6.2 R15.1 R19.1 R20.1 R21.1 R22.1 R23.1 R26.1 R30.1 R34.1 R36.1 R37.2 R42.1 R43.1 R48.1 R52.1 R54.2 R61.2 R62.2 R67.1 R70.1 R78.1 R81.1 R131.1 R132.1 R133.1 R134.1 R135.2 R136.2 R183.1 R185.2 SW2.1 SW2.3 T1.9 T1.10 TP3.1 TP9.1 TP19.1 TP22.1 U3.2 U3.3 U3.9 U4.33 U5.3 U6.2 U7.4 U8.2 U9.6 U9.7 U10.2 U11.2 U11.10 U11.25 U14.2 U14.5 U15.2 U15.3 U15.9 U61.5 U61.11 U61.20 U61.21 U62.3 U62.10 X1.2 X1.4 | length 2131.3
  Top Copper w4: J8.A12@4580.71,838.08 4580.71,820.37 4591.04,810.04 4592.52,810.04
  Top Copper w5: Q4.2@1769.31,859.02 1770.02,859.02 1783,872 v6(1783,902)
  Top Copper w6: C27.1@1443.53,603.1 1443.53,616.87 1462.92,636.26 1462.92,654.08 U11.25@1464.84,656 1464.84,689 ; 1464.84,750.75 U11.10@1464.84,779.04 ; C28.1@1519.75,603.1 1555.15,603.1 C19.1@1557.25,601
  Top Copper w10: J9.31@165.21,768.34 v2(165.21,789.59) ; R62.2@1307.09,1024.17 1308,1023.25 v2(1308,1009.59) ; C27.1@1443.53,603.1 1442.74,603.1 1421.13,581.49 1421.13,517.58 1430.71,508 1536.8,508 1555.8,527 1556,527 ; U11.2@1546.04,687.99 1560.01,687.99 v5(1571,677) ; v2(1585.2,660) 1590.95,654.25 C17.1@1607,654.25 ; v2(2133.01,795) 2133.71,795 J6.31@2133.71,768.34 ; v2(4168.81,788.87) 4179.9,788.87 4188.94,797.92 D10.3@4207.97,797.92 D10.8@4240.85,797.92 v2(4261.81,797.92) ; v2(4184.77,917.72) 4189.1,913.39 D9.3@4209.02,913.39 D9.8@4241.9,913.39 v2(4264.78,913.39) ; U8.2@4763.78,690.94 v4(4794,690.94) ; U14.5@5451.53,836.61 5455.98,836.61 U14.2@5468.78,849.41 v6(5468.78,866.91)
  Bottom Copper w4: C76.1@3949.51,634.14 3953.45,638.08 U62.10@3983.92,638.08
  Bottom Copper w6: 1102,1006.14 1104.2,1003.94 J2.44@1131.69,1003.94 ; 1102,1051.18 J2.50@1131.69,1051.18 ; 1102.52,1224.41 J2.72@1131.69,1224.41 ; v2@1105.2,1255.91 J2.76@1131.69,1255.91 ; 1113.41,1303.38 1131.46,1303.38 J2.82@1131.69,1303.15 ; J2.8@1131.69,720.47 v4@1168,720.47 ; J2.14@1131.69,767.72 v4@1162.88,767.72 ; J2.20@1131.69,814.96 1160.88,814.96 1161,815.08 ; J2.26@1131.69,862.2 1132.24,861.66 1151.22,861.66 1160.88,852 ; J2.30@1131.69,893.7 1152.21,893.7 v5(1159.51,901) ; J2.88@1131.69,1350.39 1156.49,1350.39 1160,1353.91 1160,1397.64 ; J2.94@1131.69,1397.64 1160,1397.64 ; 1132,1457 1131.69,1456.69 J2.100@1131.69,1444.88 1154.25,1444.88 1160,1439.13 ; 1143,1462 1149.72,1455.28 1149.72,1455 1160,1444.72 1160,1439.13 ; 1218,864 1219.8,862.2 J2.25@1252.95,862.2 ; v4@1219,769.92 1221.2,767.72 J2.13@1252.95,767.72 ; v4@1221,720.03 1252.51,720.03 J2.7@1252.95,720.47 ; 1221.91,815.08 1252.84,815.08 J2.19@1252.95,814.96 ; 1223,910 1223.55,909.45 J2.31@1252.95,909.45 ; 1229.17,671 1231.4,673.23 J2.1@1252.95,673.23 ; v2@1251,1459 J2.99@1251,1445.43 ; J2.43@1252.95,1003.94 1302.35,1003.94 v2(1308,1009.59) ; J2.53@1252.95,1082.68 1283.32,1082.68 1285,1081 ; J2.71@1252.95,1224.41 1253.25,1224.7 1277.7,1224.7 v5(1278,1225) ; J2.75@1252.95,1255.91 1253.5,1256.45 1272.29,1256.45 1275.29,1259.45 v5(1278,1259.45) ; J2.81@1252.95,1303.15 1317.85,1303.15 1326.56,1294.44 ; J2.87@1252.95,1350.39 1229,1350.39 1224.39,1355 v2@1224.39,1396.06 ; J2.93@1252.95,1397.64 1225.97,1397.64 v2@1224.39,1396.06 ; 1160,1397.64 1160,1439.13 ; v2@1224.39,1396.06 1224.39,1437.15 1233,1445.76 1233.34,1445.43 J2.99@1251,1445.43 ; J2.99@1251,1445.43 1252.41,1445.43 J2.99@1252.95,1444.88 1251.54,1444.88 J2.99@1251,1445.43
  Bottom Copper w10: -325,800 -279.75,800 v2(-268.54,811.21) ; v2(-250,811.21) -236.79,798 -207,798 ; U6.2@1381.77,1092.12 v2(1381.77,1116)
  other v1: -250.39,500 -200.39,500 6599.61,500 -70.72,501.41 -225.39,550 6574.61,550 -152.41,583.1 10.97,583.1 5699.61,600 5749.61,600 5799.61,600 6549.61,600 6599.61,600 5724.61,650 6574.61,650 6624.61,650 -70.72,664.8 -500.39,700 5699.61,700 5849.61,700 6649.61,700 6699.61,700 6749.61,700 3374.61,750 3424.61,750 3474.61,750 3524.61,750 3574.61,750 3624.61,750 5424.61,750 5474.61,750 5524.61,750 5574.61,750 5624.61,750 6624.61,750 6674.61,750 6724.61,750 6774.61,750 5599.61,800 6549.61,800 6599.61,800 6649.61,800 6699.61,800 6749.61,800 6424.61,850 6474.61,850 6524.61,850 6574.61,850 6624.61,850 6674.61,850 6724.61,850 6774.61,850 5649.61,900 6399.61,900 6449.61,900 6499.61,900 6549.61,900 6599.61,900 6649.61,900 6699.61,900 6749.61,900 5874.61,950 6174.61,950 6324.61,950 6374.61,950 6424.61,950 6474.61,950 6524.61,950 6574.61,950 6624.61,950 6674.61,950 6724.61,950 6774.61,950 2749.61,1000 6199.61,1000 6299.61,1000 6349.61,1000 6399.61,1000 6449.61,1000 6499.61,1000 6549.61,1000 6599.61,1000 6649.61,1000 -25.39,1050 2724.61,1050 6324.61,1050 6374.61,1050 6424.61,1050 6474.61,1050 6524.61,1050 6574.61,1050 6624.61,1050 2649.61,1100 2699.61,1100 2749.61,1100 4849.61,1100 4899.61,1100 5099.61,1100 5499.61,1100 5749.61,1100 5799.61,1100 5849.61,1100 5899.61,1100 6299.61,1100 6349.61,1100 6399.61,1100 6449.61,1100 6499.61,1100 6549.61,1100 6599.61,1100 6649.61,1100 74.61,1150 274.61,1150 424.61,1150 474.61,1150 524.61,1150 574.61,1150 2074.61,1150 2124.61,1150 2174.61,1150 2224.61,1150 2274.61,1150 2324.61,1150 2374.61,1150 2424.61,1150 2474.61,1150 2524.61,1150 2574.61,1150 2624.61,1150 4824.61,1150 4874.61,1150 5074.61,1150 5124.61,1150 5774.61,1150 6324.61,1150 6374.61,1150 6424.61,1150 6474.61,1150 6524.61,1150 6774.61,1150 4849.61,1200 5099.61,1200 5149.61,1200 5749.61,1200 6199.61,1200 6299.61,1200 6349.61,1200 6399.61,1200 6449.61,1200 6499.61,1200 6749.61,1200 324.61,1250 374.61,1250 424.61,1250 474.61,1250 524.61,1250 624.61,1250 4824.61,1250 4874.61,1250 5124.61,1250 5274.61,1250 6324.61,1250 6374.61,1250 6424.61,1250 6474.61,1250 6524.61,1250 6724.61,1250 6774.61,1250 4849.61,1300 5249.61,1300 5299.61,1300 5749.61,1300 5799.61,1300 5899.61,1300 5999.61,1300 6199.61,1300 6299.61,1300 6349.61,1300 6399.61,1300 6449.61,1300 6499.61,1300 6549.61,1300 6699.61,1300 6749.61,1300 5674.61,1350 5724.61,1350 5774.61,1350 5824.61,1350 5874.61,1350 6124.61,1350 6324.61,1350 6374.61,1350 6424.61,1350 6474.61,1350 6524.61,1350 6574.61,1350 6724.61,1350 6774.61,1350 4849.61,1400 5699.61,1400 5749.61,1400 5799.61,1400 5949.61,1400 6099.61,1400 6249.61,1400 6299.61,1400 6349.61,1400 6399.61,1400 6449.61,1400 6499.61,1400 6549.61,1400 6749.61,1400 5524.61,1450 5574.61,1450 5624.61,1450 5924.61,1450 6224.61,1450 6274.61,1450 6324.61,1450 6374.61,1450 6424.61,1450 6474.61,1450 6524.61,1450 6574.61,1450 6774.61,1450 882.03,1454.17 5599.61,1500 5649.61,1500 5999.61,1500 6149.61,1500 6199.61,1500 6249.61,1500 6299.61,1500 6349.61,1500 6399.61,1500 6449.61,1500 6499.61,1500 6549.61,1500 6599.61,1500 800.34,1535.86 963.73,1535.86 474.61,1550 5824.61,1550 6074.61,1550 6124.61,1550 6174.61,1550 6224.61,1550 6274.61,1550 6324.61,1550 6374.61,1550 6424.61,1550 6474.61,1550 6524.61,1550 6574.61,1550 -250.39,1600 -200.39,1600 149.61,1600 199.61,1600 249.61,1600 299.61,1600 6049.61,1600 6099.61,1600 6149.61,1600 6199.61,1600 6249.61,1600 6299.61,1600 6349.61,1600 6399.61,1600 6449.61,1600 6499.61,1600 6549.61,1600 6599.61,1600 882.03,1617.55
  other v2: -353,494 1700,516.41 1723,516.41 2021,517 468,528 522,528 4746,548 1826,561 1583,572 232,578 2815,580 2951,580.3 2197.35,582 4704.72,587.82 -258,594 -363.67,614 4983,615.23 4933,616 4155.98,617.56 760,624 786,624 255.91,627.86 1991.43,630.89 1808,636 4909,640 4957,640 -546,658 4267,665.02 -325,666 5874,672 4161.46,673.23 -449,674 524,675.42 544,675.42 564,675.42 2295.26,694.68 389.91,699 484.4,699 507,699 885,717 907,716.89 929,716.89 1287.82,723 1452,730 1407.46,731.14 2002,739 3000,742 2246.21,746.75 2180.95,749.33 29,750.42 5872,751 809,767 833,767 29,768.52 629,775 650,775 671,775 693,775 -549,778 2698,783 2999,794 2201,795 2237,795 2305,795 320.33,811.71 363,811.71 403,812 29,814 200.93,822.23 1581,852.89 4161.13,877.95 -369,901.57 -551,911 -171,922 5797,930 4136,933.95 -426,983.86 -550,990 1224,1008 -370.03,1020 5681,1029 -426,1038 -551,1053 -368,1076 903,1101.29 1283.82,1104 -551,1121 869,1158 -290.42,1185.61 934,1186 -551,1193 3080,1211 3195,1216.54 798,1224 1421.39,1226.86 1223,1230.39 1099.17,1251.46 -552,1255 660,1257 1384,1267 624,1296 1087,1301 1342.48,1302 1395,1302.38 897,1306.69 991.8,1306.69 2884,1325.68 1910,1328.39 2392,1333 -551,1341 1517.18,1344.39 1393,1344.88 3195,1347.48 1282.38,1348.62 3110,1351.41 -138,1360.58 770,1368.72 842,1368.72 1585.46,1369.58 -496,1372.16 1851.02,1375 1636,1389.47 1066.36,1400.26 1224.85,1400.26 1755,1402 -174,1404 2441,1405 2883,1405 703,1409.45 776,1409 1636,1414 1812.94,1414 305,1420 376,1421 552,1422 -364,1424 613,1424.7 -549,1429 -496,1438 1718.15,1440 -173,1455 1251,1456.03 -395,1458.03 -547,1480 1044.15,1484 1249.29,1510 1479,1511.81 1580.77,1511.81 1619.73,1511.81 1140,1513.73 -382,1515 1413,1532.65 1326,1547 1274,1550 -383.01,1560 3382,1565 3587,1575.18 -331,1595 -307,1595 -36,1609 421,1619 -395,1623.02 3635,1623.46 3386,1625 3573,1625 -321,1626 -115,1627 37,1630
  other v4: 5364.17,571.48 2439,580.12 5075,591.15 5327.83,605.17 5075,613.48 1420,624 3931,634.18 2837,643.48 2866,643.48 2501.31,671.48 2523.22,671.48 6433,670.95 6457.23,671.83 4680.62,689.96 2210,695 3957,696.95 3900,699.26 6263.75,704.28 6086,704.98 2386,710 1159.74,720.47 1224.17,720.03 5068.74,727.17 4225.46,734.48 2386,735.95 6275,735.81 4160.24,741.21 6157.35,742.37 5047.24,748.48 2619,750 3926.16,761.97 1161,767 1225,767 5361,772.48 2591,779 5074,779.48 5901,784.48 5074,800.48 6117.96,802.48 6188.83,802.48 5901,807.29 599,854.33 677,853.93 4266,854.96 2436.29,867.11 2690,902.48 2586,911.48 3925.65,911.95 2641,913.89 5036.42,920.39 5066,920.39 2586,937.48 1409,959 2639,977.48 788,981.78 2660.33,999.22 682,1000 594,1001 1613,1074 1722.74,1080.21 1440.94,1159.43 1481,1401 5798,1448.95 1482,1456 -354,1468.95 5844,1488.95 5971,1547.95 6012,1584.95
  other v5: 339,699 179,707 231,707 179,732.28 339,743
  other v7: 5125.98,647.94 5125.98,687.31 5125.98,834.65 5125.98,874.02 1615.46,1225.36 1654.83,1225.36 1615.46,1264.73 1654.83,1264.73
GPIO7/sd_hst_cd: J2.59 R66.2 | length 245
  Top Copper w6: v3(1283.46,1129.92) 1317.23,1129.92 1332.98,1114.17 1332.98,958.96 R66.2@1330.71,956.69
  Bottom Copper w6: J2.59@1252.95,1129.92 v3(1283.46,1129.92)
HSO: R8.2 U1.10 | length 165.5
  Top Copper w5.91: v3(3944.88,1096.18) 3947.2,1096.18 3954.96,1103.94 3994.85,1103.94 4037.53,1146.62 U1.10@4037.53,1161.42
  Bottom Copper w5.91: R8.2@3935.17,1062.99 3944.88,1072.71 v3(3944.88,1096.18)
I2C0_SCL: J3.34 TP1.1 U7.6 | length 511.1
  Top Copper w4: TP1.1@-359.26,1353.94 -353.94,1353.94 -323.71,1323.71 -323.71,1266.84
  Top Copper w6: v3(-362.2,1228.35) -323.71,1266.84 -282.59,1266.84 -268.7,1252.95 U7.6@-268.7,1232.28
  Bottom Copper w6: v3(-362.2,1228.35) -402,1188.55 -402,1059 -386.31,1043.31 J3.34@-324.02,1043.31
I2C0_SDA: J3.36 TP2.1 U7.5 | length 378
  Top Copper w4: v3(-362.13,1197.32) -362.28,1197.32 -376.2,1211.24 -376.2,1242.4 -358.27,1260.34 TP2.1@-358.27,1273.62
  Top Copper w6: v3(-362.13,1197.32) -327.17,1232.28 U7.5@-294.29,1232.28
  Bottom Copper w6: v3(-362.13,1197.32) -362.13,1194.61 -386,1170.74 -386,1066 -379.06,1059.06 J3.36@-324.02,1059.06
I2C1_SCL: J2.35 J6.7 | length 1367.8
  Top Copper w4: v3(2413.39,807.85) 2415.28,805.96 2415.28,770.23 J6.7@2417.17,768.34
  Signal Layer 4 w4: v3(1353.41,972.27) 1354.17,972.27 1361.74,964.69 1369.58,964.69 1417.89,1013 2282.28,1013 2415.57,879.7 2415.57,810.04 v3(2413.39,807.85)
  Bottom Copper w4: J2.35@1252.95,940.94 1284.9,940.94 1310.19,966.24 1347.38,966.24 v3(1353.41,972.27)
I2C1_SDA: J2.33 J6.5 | length 1360.9
  Top Copper w4: v3(2401.57,870.08) 2404.09,870.08 2440.8,833.37 J6.5@2440.8,768.34
  Signal Layer 4 w4: v3(1353.54,952.27) 1356.78,952.27 1361.2,956.69 1372.9,956.69 1421.2,1005 2266.65,1005 v3(2401.57,870.08)
  Bottom Copper w4: J2.33@1252.95,925.2 1281.72,925.2 1313.52,957 1348.8,957 v3(1353.54,952.27)
I2C2_SCL: J2.77 J10.7 | length 5685.1
  Top Copper w4: v2(5704.72,1049.43) 5735.16,1019 5906.06,1019 6047.36,877.7 6295.53,877.7 6354.18,819.05 J10.7@6354.18,768.34
  Signal Layer 2 w4: v3(1224.77,1271.8) 1236.09,1283.12 1236.09,1341.9 1372.42,1478.22 3190.58,1478.22 3338.1,1330.71 3633.86,1330.71 3795.28,1169.29 3795.28,1096.72 3892.39,999.61 4915.37,999.61 4965.2,1049.43 v2(5704.72,1049.43)
  Bottom Copper w6: v3(1224.77,1271.8) 1224.85,1271.73 J2.77@1252.95,1271.65 J2.77@1252.95,1271.65
I2C2_SDA: J2.79 J10.5 | length 5708.2
  Top Copper w4: v2(5704.72,1069.43) 5704.72,1069.23 5743.96,1030 5906.37,1030 6050.67,885.7 6298.84,885.7 6377.8,806.74 J10.5@6377.8,768.34
  Signal Layer 2 w4: v3(1222.09,1296.4) 1222.09,1339.21 1369.1,1486.22 3193.9,1486.22 3337.6,1342.52 3637.8,1342.52 3805.1,1175.22 3805.1,1099.85 3895.95,1009 4909,1009 4959.06,1059.06 5694.35,1059.06 v2(5704.72,1069.43)
  Bottom Copper w4: v3(1222.09,1296.4) 1224.39,1294.1 1236.01,1294.1 1242.72,1287.4 J2.79@1252.95,1287.4
I2C3_SCL: J2.78 J5.2 J9.7 | length 3748.6
  Top Copper w4.02: v3(1192,1589.1) 1202.25,1599.35 2618.58,1599.35 2627.93,1590 2630.47,1590 2822.83,1397.64 2822.83,864.51 2842.01,845.33 2842.01,830.09 v3(2841.87,829.94) ; v3(2874.02,829.94) 2923.6,829.94 J5.2@2928.15,825.39
  Top Copper w5: J9.7@448.67,768.34 448.67,788.67 487,827 680,827 923.58,1070.58 923.58,1144.06 970.52,1191 1041.55,1191 v2(1050.55,1182)
  Bottom Copper w4.02: J2.78@1131.69,1271.65 1172.04,1271.65 1183.35,1282.96 1183.35,1580.45 v3(1192,1589.1) ; v3(2841.87,829.94) v3(2874.02,829.94)
  Bottom Copper w5: v2(1050.55,1182) 1039,1193.55 1039,1232.9 1077.75,1271.65 J2.78@1131.69,1271.65
I2C3_SDA: J2.80 J5.4 J9.5 | length 3761
  Top Copper w4.02: v3(1181,1607) 1182,1608 2623.81,1608 2830.85,1400.96 2830.85,889.62 2855.87,864.6 2855.87,822.4 2870.31,807.97 2870.31,800.95 2895.87,775.39 J5.4@2928.15,775.39
  Top Copper w5: J9.5@472.29,768.34 472.29,790.29 497,815 684,815 936,1067 936,1138 977,1179 1014.96,1179 v2(1027,1166.96)
  Bottom Copper w4.02: J2.80@1131.69,1287.4 1169.71,1287.4 1175.2,1292.89 1175.2,1601.2 v3(1181,1607)
  Bottom Copper w5: v2(1027,1166.96) 1027,1233.63 1074.37,1281 1113,1281 1119.4,1287.4 J2.80@1131.69,1287.4
I2C4_SCL_1V8: J3.59 P1.3 | length 931.3
  Top Copper w5: P1.3@-306.43,818.06 -293.98,830.5 v2(-258.97,830.5)
  Signal Layer 2 w5: v2(-258.97,830.5) -340.5,830.5 -407,897 -407,1254.64 -392.64,1269 -298.3,1269 -236,1206.7 -236,1183.09 v2(-246.04,1173.05)
  Bottom Copper w5: v2(-246.04,1173.05) -246.04,1173.9 -238.45,1181.48 -238.45,1232.89 -223.31,1248.03 J3.59@-202.76,1248.03
I2C4_SDA_1V8: J3.57 P1.2 | length 1015.2
  Top Copper w5: P1.2@-406.43,699.94 -406.43,826.43 -529,949 -529,1147.77 -432.77,1244 v7(-390.27,1244)
  Signal Layer 2 w5: v7(-390.27,1244) -374.27,1260 -302.02,1260 -272.42,1230.4 v7(-272.42,1173.42)
  Bottom Copper w5: v7@-272.06,1173.05 v7(-272.42,1173.42) -272.42,1172.83 -258.14,1158.55 -232.83,1158.55 -229.45,1161.93 -229.45,1225.23 -222.39,1232.28 J3.57@-202.76,1232.28
ISNS: R13.1 TP10.1 U1.1 U1.8 | length 398.2
  Top Copper w4: TP10.1@3870.08,1257.32 3896.52,1257.32 3909.45,1270.25 3952.19,1270.25 R13.1@3952.76,1269.69
  Top Copper w5.91: R13.1@3952.19,1270.25 v3(3952.19,1305.82) ; U1.1@4153.67,1277.56 4153.67,1286.42 4162.13,1294.87 4162.13,1303.89 v3(4164.06,1305.82)
  Signal Layer 2 w5.91: v3(3952.19,1305.82) 3988.33,1305.82 4022.49,1339.97 4132.73,1339.97 4159.46,1313.25 4159.46,1313.15 4164.06,1308.55 v3(4164.06,1305.82)
LED0_10_GRN: R57.1 U4.27 | length 695.8
  Top Copper w5: U4.27@1611.52,1171.22 1611.52,1102.34 1581,1071.83 1581,915.4 1590.4,906 1728.07,906 1751.07,929 1821,929 1841.97,908.03 R57.1@1841.97,763.78
LED0_10_GRN1: D16.1 R57.2 | length 42.3
  Top Copper w4: D16.1@1841.97,682.09 R57.2@1841.97,724.41
LED1_100_OR: R58.1 U4.26 | length 1860.7
  Top Copper w4: v2@1595.77,1145.32 U4.26@1595.77,1171.22
  Top Copper w5: v6(3024,901) 3024,630.57 R58.1@3048.33,606.24
  Signal Layer 2 w5: v2(1595.96,1145.13) 1636.09,1105 1798.71,1105 1802.71,1101 2586,1101 2787,900 3023,900 v6(3024,901)
LED1_100_OR1: J1.18 R58.2 | length 724.2
  Top Copper w5: R58.2@3087.7,606.24 3087.7,580.3 3105.01,562.99 3675.73,562.99 J1.18@3748.62,635.89
LED2_1000_GRN: R59.1 U4.25 | length 1810.1
  Top Copper w4: U4.25@1580.02,1171.22 1580.02,1137.98 v3(1595,1123) ; v3(1894.7,1069.12) 1895.3,1068.52 2299.99,1068.52 2507.51,861 2638.1,861 v3(2671.86,827.23) ; v3(3048,807.97) 3048.33,807.63 R59.1@3048.33,644.41
  Bottom Copper w4: v3(1595,1123) 1596,1123 1615.65,1103.35 1875,1103.35 1894.7,1083.65 v3(1894.7,1069.12) ; v3(2671.86,827.23) 2683.15,815.94 2993.8,815.94 3040.02,815.94 v3(3048,807.97)
LED2_1000_GRN1: J1.16 R59.2 | length 294.2
  Top Copper w5: R59.2@3087.7,644.41 3087.7,642.45 3155.35,574.8 3265.49,574.8 J1.16@3326.57,635.89
MD1_N: D17.2 D17.9 J1.2 U4.2 | length 2405.7
  Top Copper w5.12: U4.2@1708.96,1205.67 1719.55,1205.67 1722.36,1202.86 1760.46,1202.86 1761.34,1201.97 1773.03,1201.97 1779.72,1208.66 v3(1783.46,1208.66)
  Bottom Copper w5.12: v3(1783.46,1208.66) 1786.4,1208.66 1791.76,1203.31 1809.37,1203.31 1810.87,1204.81 1810.87,1249.67 1865.33,1304.13 1989.94,1304.13 2038.72,1304.13 cw(c2038.72,1276.97) 2065.88,1276.97 2065.88,1238.88 ccw(c2080.25,1238.88) 2080.25,1224.51 ccw(c2080.25,1238.88) 2094.62,1238.88 2094.62,1283.86 cw(c2121.78,1283.86) 2121.78,1311.02 cw(c2121.78,1283.86) 2148.95,1283.86 2148.95,1238.88 ccw(c2163.32,1238.88) 2163.32,1224.51 ccw(c2163.32,1238.88) 2177.69,1238.88 2177.69,1283.86 cw(c2204.85,1283.86) 2204.85,1311.02 cw(c2204.85,1283.86) 2232.01,1283.86 2232.01,1238.88 ccw(c2246.38,1238.88) 2246.38,1224.51 ccw(c2246.38,1238.88) 2260.75,1238.88 2260.75,1283.86 cw(c2287.91,1283.86) 2287.91,1311.02 cw(c2287.91,1283.86) 2315.07,1283.86 2315.07,1238.88 ccw(c2329.44,1238.88) 2329.44,1224.51 ccw(c2329.44,1238.88) 2343.81,1238.88 2343.81,1276.97 cw(c2370.97,1276.97) 2370.97,1304.13 2379.92,1304.13 2896.66,1304.13 3007.38,1193.4 3117.91,1193.4 3121.36,1196.85 D17.2@3128.54,1196.85 D17.9@3161.42,1196.85 3168.6,1196.85 3172.05,1193.4 3221.02,1193.4 3224.86,1197.24 3283.31,1197.24 3318.66,1161.88 3318.66,1108.91 3311.92,1102.16 3311.92,1087.01 3314.48,1084.45 3314.48,1047.61 J1.2@3312.6,1045.73
MD1_P: D17.1 D17.10 J1.1 U4.1 | length 2403.8
  Top Copper w5.12: U4.1@1708.96,1189.92 1719.55,1189.92 1722.36,1192.74 1756.27,1192.74 1757.15,1191.85 1773.03,1191.85 1779.72,1185.16 v3(1783.46,1185.16)
  Bottom Copper w5.12: v3(1783.46,1185.16) 1786.4,1185.16 1791.76,1190.52 1814.67,1190.52 1823.66,1199.51 1823.66,1244.37 1870.63,1291.34 1989.94,1291.34 2038.72,1291.34 cw(c2038.72,1276.97) 2053.09,1276.97 2053.09,1238.88 ccw(c2080.25,1238.88) 2080.25,1211.72 ccw(c2080.25,1238.88) 2107.41,1238.88 2107.41,1283.86 cw(c2121.78,1283.86) 2121.78,1298.23 cw(c2121.78,1283.86) 2136.15,1283.86 2136.15,1238.88 ccw(c2163.32,1238.88) 2163.32,1211.72 ccw(c2163.32,1238.88) 2190.48,1238.88 2190.48,1283.86 cw(c2204.85,1283.86) 2204.85,1298.23 cw(c2204.85,1283.86) 2219.22,1283.86 2219.22,1238.88 ccw(c2246.38,1238.88) 2246.38,1211.72 ccw(c2246.38,1238.88) 2273.54,1238.88 2273.54,1283.86 cw(c2287.91,1283.86) 2287.91,1298.23 cw(c2287.91,1283.86) 2302.28,1283.86 2302.28,1238.88 ccw(c2329.44,1238.88) 2329.44,1211.72 ccw(c2329.44,1238.88) 2356.6,1238.88 2356.6,1276.97 cw(c2370.97,1276.97) 2370.97,1291.34 2379.92,1291.34 2891.36,1291.34 2896.96,1285.74 2898.77,1283.93 2913.52,1269.17 cw(c2906.15,1261.8) 2913.52,1254.42 2910.09,1250.99 ccw(c2917.47,1243.61) 2910.09,1236.23 ccw(c2917.47,1243.61) 2924.85,1236.23 2928.28,1239.67 cw(c2935.66,1232.29) 2943.03,1239.67 2955.15,1227.55 2956.96,1225.74 3002.09,1180.61 3117.91,1180.61 3121.36,1177.17 D17.1@3128.54,1177.17 D17.10@3161.42,1177.17 3168.6,1177.17 3172.05,1180.61 3226.32,1180.61 3230.16,1184.45 3278.01,1184.45 3305.87,1156.59 3305.87,1114.21 3302.87,1111.21 3298.63,1111.21 3264.11,1145.73 J1.1@3262.6,1145.73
